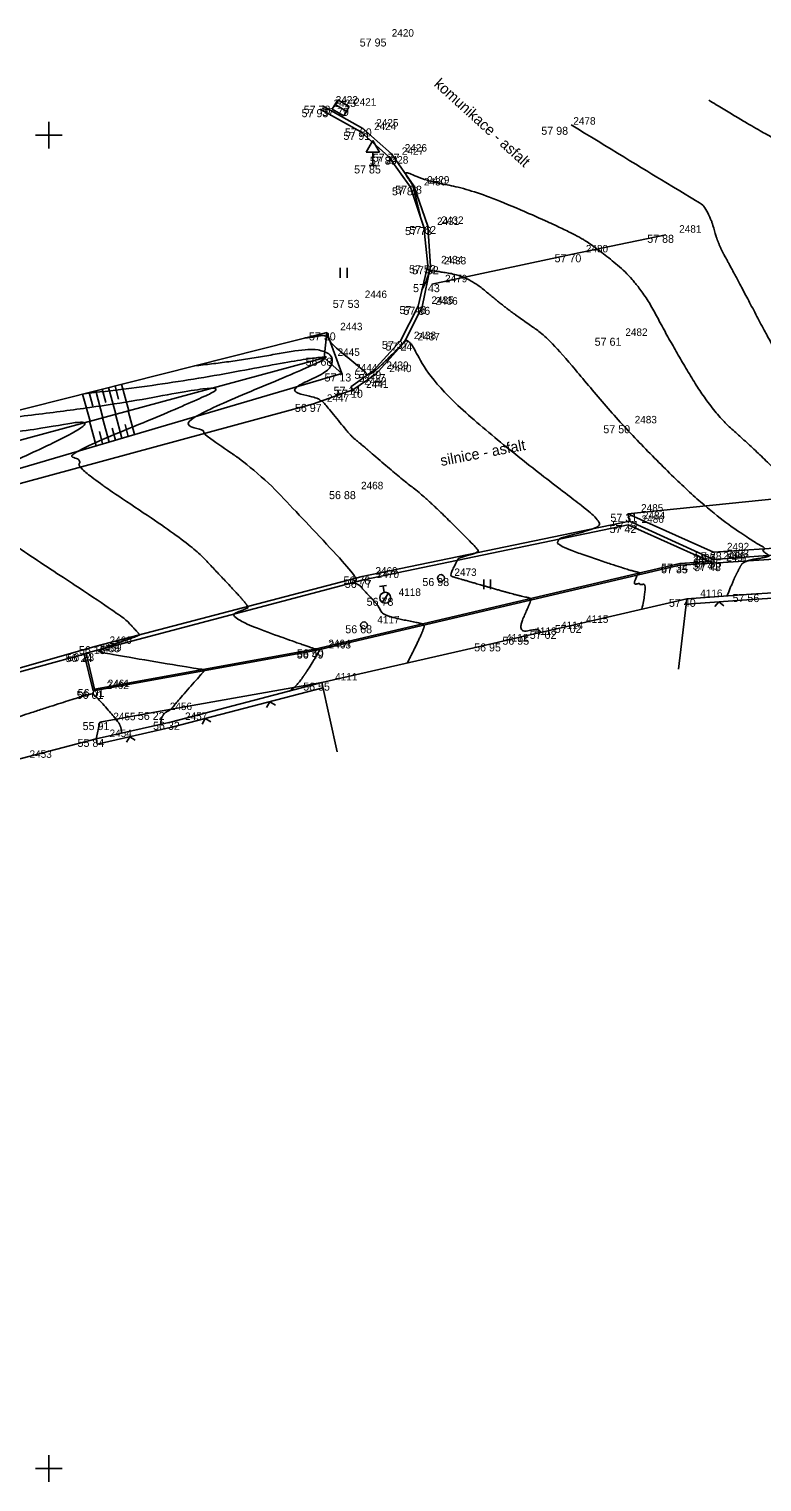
# Model space of a CAD drawing. Extents: x -704017 to -701500, y -1008977 to -1008450.
# Drawn here: x -702650.7 to -702623.3, y -1008800.5 to -1008746 of the extents above; entities that cross this region are included whole.
import ezdxf

# ---------------------------------------------------------------- set-up
doc = ezdxf.new("R2010")
doc.units = 0
for name, color, linetype in [('Z_ACO', 7, 'Continuous'), ('Z_body', 7, 'Continuous'), ('Z_body_cisla', 7, 'Continuous'), ('Z_body_vysky', 7, 'Continuous'), ('Z_budovy', 7, 'Continuous'), ('Z_chodnik', 7, 'Continuous'), ('Z_dopravni_znaceni', 7, 'Continuous'), ('Z_hekt_sit', 7, 'Continuous'), ('Z_komunikace', 7, 'Continuous'), ('Z_obruby', 7, 'Continuous'), ('Z_oploceni', 7, 'Continuous'), ('Z_popis', 7, 'Continuous'), ('Z_rozhrani_ploch', 7, 'Continuous'), ('Z_site_znaky_kanalizace', 7, 'Continuous'), ('Z_site_znaky_vodovod', 7, 'Continuous'), ('Z_teren_hrany_paty', 7, 'Continuous'), ('Z_vrstevnice_hlavni', 7, 'Continuous'), ('Z_vrstevnice_vedlejsi', 7, 'Continuous'), ('Z_vstupy', 7, 'Continuous')]:
    doc.layers.add(name, color=color, linetype=linetype)

# ---------------------------------------------------------------- blocks, each defined once
blk = doc.blocks.new('POINT_DISPLAY')
blk.add_line((0, 0), (0, 0))
blk = doc.blocks.new('Z212')
for p, q in [((-0.17, 0.17), (0, 0)), ((0, 0), (0.17, 0.17))]:
    blk.add_line(p, q)
blk = doc.blocks.new('Z306')
for p, q in [((-0.13, 0.17), (-0.13, -0.2)), ((0.13, 0.17), (0.13, -0.2))]:
    blk.add_line(p, q)
blk = doc.blocks.new('Z527')
for p, q in [((0, 0.93), (-0.25, 0.5)), ((0.25, 0.5), (0, 0.93)), ((-0.25, 0.5), (0.25, 0.5)), ((-0.13, 0), (0.13, 0)), ((0, 0), (0, 0.5))]:
    blk.add_line(p, q)
blk = doc.blocks.new('Z38')
for p, q in [((0.25, 0.2), (-0.25, 0.2)), ((-0.25, 0.2), (-0.25, -0.2)), ((-0.25, 0), (0.25, 0)), ((0.25, -0.2), (0.25, 0.2)), ((-0.25, -0.2), (0.25, -0.2))]:
    blk.add_line(p, q)
blk = doc.blocks.new('Z614')
for p, q in [((-0.13, 0.03), (-0.1, 0.08)), ((-0.13, -0.03), (-0.13, 0.03)), ((-0.1, 0.08), (-0.08, 0.1)), ((-0.08, 0.1), (-0.03, 0.13)), ((-0.03, 0.13), (0.03, 0.13)), ((0.03, 0.13), (0.08, 0.1)), ((0.08, 0.1), (0.1, 0.08)), ((0.1, 0.08), (0.13, 0.03)), ((0.13, 0.03), (0.13, -0.03)), ((-0.1, -0.08), (-0.13, -0.03)), ((-0.08, -0.1), (-0.1, -0.08)), ((-0.03, -0.13), (-0.08, -0.1)), ((0.03, -0.13), (-0.03, -0.13)), ((0.08, -0.1), (0.03, -0.13)), ((0.1, -0.08), (0.08, -0.1)), ((0.13, -0.03), (0.1, -0.08))]:
    blk.add_line(p, q)
blk = doc.blocks.new('Z18')
for p, q in [((-0.2, 0.05), (-0.15, 0.15)), ((-0.2, -0.05), (-0.2, 0.05)), ((-0.15, 0.15), (-0.05, 0.2)), ((0.15, 0.15), (-0.15, -0.15)), ((-0.13, 0.45), (0.13, 0.45)), ((-0.05, 0.2), (0.05, 0.2)), ((0, 0.2), (0, 0.45)), ((0.05, 0.2), (0.15, 0.15)), ((0.15, 0.15), (0.2, 0.05)), ((0.2, 0.05), (0.2, -0.05)), ((-0.15, -0.15), (-0.2, -0.05)), ((-0.05, -0.2), (-0.15, -0.15)), ((0.05, -0.2), (-0.05, -0.2)), ((0.15, -0.15), (0.05, -0.2)), ((0.2, -0.05), (0.15, -0.15))]:
    blk.add_line(p, q)

msp = doc.modelspace()

# ---------------------------------------------------------------- linework, layer by layer
at = {"layer": 'Z_ACO'}
for p, q in [((-702630.36, -1008754.47), (-702626.86, -1008753.74)), ((-702635.64, -1008755.59), (-702630.36, -1008754.47))]:
    msp.add_line(p, q, dxfattribs=at)
at = {"layer": 'Z_budovy'}
for p, q in [((-702630.35, -1008768.37), (-702626.07, -1008767.39)), ((-702626.39, -1008770.03), (-702626.07, -1008767.39)), ((-702639.76, -1008770.53), (-702633.35, -1008769.06)), ((-702632.29, -1008768.81), (-702631.29, -1008768.59)), ((-702639.76, -1008770.53), (-702639.18, -1008773.12))]:
    msp.add_line(p, q, dxfattribs=at)
at = {"layer": 'Z_chodnik'}
for p, q in [((-702640, -1008769.33), (-702626.34, -1008766.13)), ((-702626.34, -1008766.13), (-702625.1, -1008766.05)), ((-702648.67, -1008769.46), (-702648.33, -1008770.84)), ((-702648.33, -1008770.84), (-702640, -1008769.33)), ((-702645.96, -1008771.63), (-702639.76, -1008770.53)), ((-702648.08, -1008772.01), (-702645.96, -1008771.63)), ((-702648.08, -1008772.01), (-702648.22, -1008772.64))]:
    msp.add_line(p, q, dxfattribs=at)
at = {"layer": 'Z_hekt_sit'}
for p, q in [((-702650.5, -1008750), (-702649.5, -1008750)), ((-702650, -1008749.5), (-702650, -1008750.5)), ((-702650, -1008799.5), (-702650, -1008800.5)), ((-702650.5, -1008800), (-702649.5, -1008800))]:
    msp.add_line(p, q, dxfattribs=at)
at = {"layer": 'Z_komunikace'}
for p, q in [((-702639.74, -1008748.9), (-702638.22, -1008749.75)), ((-702638.22, -1008749.75), (-702637.15, -1008750.7)), ((-702637.15, -1008750.7), (-702636.31, -1008751.9)), ((-702636.31, -1008751.9), (-702635.78, -1008753.41)), ((-702635.78, -1008753.41), (-702635.68, -1008754.92)), ((-702635.68, -1008754.92), (-702636, -1008756.44)), ((-702636, -1008756.44), (-702636.67, -1008757.78)), ((-702636.67, -1008757.78), (-702637.73, -1008758.96)), ((-702637.73, -1008758.96), (-702638.6, -1008759.55)), ((-702638.6, -1008759.55), (-702640.07, -1008760.08)), ((-702655.23, -1008764.19), (-702640.07, -1008760.08)), ((-702628.29, -1008764.2), (-702616.13, -1008762.97)), ((-702638.25, -1008766.55), (-702628.22, -1008764.48)), ((-702628.22, -1008764.48), (-702628.29, -1008764.2)), ((-702648.22, -1008769.16), (-702638.25, -1008766.55)), ((-702652.66, -1008770.43), (-702648.22, -1008769.16))]:
    msp.add_line(p, q, dxfattribs=at)
at = {"layer": 'Z_obruby'}
for p, q in [((-702639.82, -1008749.03), (-702638.3, -1008749.88)), ((-702638.3, -1008749.88), (-702637.26, -1008750.81)), ((-702637.26, -1008750.81), (-702636.43, -1008751.96)), ((-702636.43, -1008751.96), (-702635.94, -1008753.45)), ((-702635.94, -1008753.45), (-702635.79, -1008754.88)), ((-702635.79, -1008754.88), (-702636.15, -1008756.41)), ((-702636.15, -1008756.41), (-702636.81, -1008757.72)), ((-702636.81, -1008757.72), (-702637.84, -1008758.84)), ((-702637.84, -1008758.84), (-702638.67, -1008759.44)), ((-702638.67, -1008759.44), (-702638.6, -1008759.55)), ((-702638.2, -1008766.68), (-702628.27, -1008764.62)), ((-702628.27, -1008764.62), (-702625.21, -1008765.99)), ((-702625.1, -1008766.05), (-702618.04, -1008765.58)), ((-702640.02, -1008769.28), (-702626.34, -1008766.07)), ((-702626.34, -1008766.07), (-702625.21, -1008765.99)), ((-702625.21, -1008765.99), (-702625.1, -1008766.05)), ((-702648.6, -1008769.43), (-702638.2, -1008766.68)), ((-702652.56, -1008770.53), (-702648.67, -1008769.46)), ((-702648.67, -1008769.46), (-702648.6, -1008769.43)), ((-702648.6, -1008769.43), (-702648.29, -1008770.77)), ((-702648.29, -1008770.77), (-702640.02, -1008769.28))]:
    msp.add_line(p, q, dxfattribs=at)
at = {"layer": 'Z_oploceni'}
for p, q in [((-702623.65, -1008767.41), (-702626.09, -1008767.59)), ((-702623.66, -1008767.21), (-702626.07, -1008767.39)), ((-702623.66, -1008767.21), (-702620.11, -1008767.01)), ((-702623.65, -1008767.41), (-702620.1, -1008767.21)), ((-702645.39, -1008772), (-702639.76, -1008770.53)), ((-702645.34, -1008772.19), (-702639.72, -1008770.73)), ((-702648.22, -1008772.64), (-702645.39, -1008772)), ((-702648.18, -1008772.84), (-702645.34, -1008772.19)), ((-702648.22, -1008772.64), (-702648.18, -1008772.84))]:
    msp.add_line(p, q, dxfattribs=at)
at = {"layer": 'Z_rozhrani_ploch'}
for p, q in [((-702628.29, -1008764.2), (-702625.07, -1008765.64)), ((-702628.22, -1008764.48), (-702625.08, -1008765.91)), ((-702625.07, -1008765.64), (-702618.08, -1008765.17)), ((-702625.08, -1008765.91), (-702618.06, -1008765.41))]:
    msp.add_line(p, q, dxfattribs=at)
at = {"layer": 'Z_teren_hrany_paty'}
for p, q in [((-702657.12, -1008761.83), (-702639.57, -1008757.4)), ((-702639.67, -1008758.35), (-702639.57, -1008757.4)), ((-702639.57, -1008757.4), (-702639.01, -1008758.94)), ((-702655.88, -1008762.74), (-702639.67, -1008758.35)), ((-702639.67, -1008758.35), (-702639.01, -1008758.94)), ((-702639.01, -1008758.94), (-702655.4, -1008763.76)), ((-702648.73, -1008759.71), (-702648.45, -1008760.73)), ((-702648.48, -1008759.65), (-702648.35, -1008760.16)), ((-702648.24, -1008759.59), (-702647.97, -1008760.6)), ((-702648, -1008759.53), (-702647.86, -1008760.03)), ((-702647.76, -1008759.47), (-702647.49, -1008760.47)), ((-702647.51, -1008759.41), (-702647.38, -1008759.9)), ((-702647.27, -1008759.34), (-702647, -1008760.34)), ((-702646.78, -1008761.23), (-702647.02, -1008760.34)), ((-702648.22, -1008761.65), (-702648.47, -1008760.73)), ((-702647.74, -1008761.51), (-702647.99, -1008760.6)), ((-702647.26, -1008761.37), (-702647.5, -1008760.47)), ((-702647.02, -1008761.3), (-702647.14, -1008760.85)), ((-702647.98, -1008761.58), (-702648.1, -1008761.12)), ((-702647.5, -1008761.44), (-702647.62, -1008760.99))]:
    msp.add_line(p, q, dxfattribs=at)
at = {"layer": 'Z_vrstevnice_hlavni'}
for points in [[(-702630.416, -1008749.616), (-702625.799, -1008752.432), (-702625.423, -1008752.633), (-702625.175, -1008753.161), (-702625.132, -1008753.263), (-702624.874, -1008754.143), (-702624.402, -1008754.984), (-702622.625, -1008758.355), (-702621.686, -1008759.908), (-702618.689, -1008762.539), (-702618.058, -1008763.165), (-702617.68, -1008763.433), (-702616.898, -1008763.837), (-702615.597, -1008764.737), (-702614.913, -1008765.015), (-702615.538, -1008765.241), (-702615.398, -1008765.284), (-702615.656, -1008765.318), (-702615.773, -1008765.464), (-702616.146, -1008766.635), (-702616.155, -1008766.801)], [(-702644.537, -1008758.654), (-702642.854, -1008758.475), (-702639.618, -1008757.86), (-702639.201, -1008758.77), (-702641.162, -1008759.573), (-702639.871, -1008759.866), (-702639.823, -1008759.967), (-702639.731, -1008759.958), (-702638.686, -1008761.277), (-702638.351, -1008761.533), (-702636.804, -1008762.872), (-702635.86, -1008763.587), (-702633.904, -1008765.525), (-702633.873, -1008765.647), (-702634.621, -1008765.848), (-702634.686, -1008765.951), (-702634.971, -1008766.52), (-702634.793, -1008766.58), (-702632.439, -1008767.26), (-702631.877, -1008767.369), (-702631.973, -1008767.427), (-702631.899, -1008767.432), (-702632.474, -1008768.694), (-702631.546, -1008768.475), (-702631.576, -1008768.653)], [(-702666.86, -1008764.305), (-702666.101, -1008764.107), (-702660.186, -1008763.092), (-702656.884, -1008762.487), (-702656.428, -1008762.338), (-702653.8, -1008762.059), (-702652.34, -1008761.781), (-702655.604, -1008763.327), (-702657.495, -1008764.162), (-702661.19, -1008765.431), (-702663.088, -1008766.219), (-702663.599, -1008766.55), (-702661.588, -1008767.639), (-702659.693, -1008768.918), (-702653.899, -1008769.76), (-702653.524, -1008770.446), (-702652.25, -1008771.87), (-702654.07, -1008772.42), (-702654.272, -1008773.671), (-702654.329, -1008773.727), (-702654.053, -1008773.693), (-702653.751, -1008773.641), (-702653.563, -1008773.532), (-702654.07, -1008772.42), (-702652.136, -1008772.219), (-702652.047, -1008772.104), (-702648.446, -1008770.943), (-702648.305, -1008770.957), (-702647.465, -1008771.9), (-702647.268, -1008772.215), (-702647.277, -1008772.427)]]:
    msp.add_open_spline(points, degree=2, dxfattribs=at)
at = {"layer": 'Z_vrstevnice_vedlejsi'}
for points in [[(-702625.246, -1008748.696), (-702623.588, -1008749.706), (-702622.428, -1008750.326), (-702621.664, -1008751.956), (-702621.534, -1008752.268), (-702620.738, -1008754.983), (-702619.282, -1008757.575), (-702618.616, -1008758.839), (-702618.263, -1008759.422), (-702616.166, -1008761.263), (-702614.267, -1008762.903), (-702613.979, -1008763.167), (-702612.493, -1008764.195), (-702610.955, -1008764.822), (-702611.336, -1008764.959), (-702610.961, -1008765.074), (-702611.65, -1008765.164), (-702611.724, -1008765.257), (-702611.96, -1008765.997), (-702611.994, -1008766.58)], [(-702636.049, -1008753.119), (-702636.203, -1008752.468), (-702636.337, -1008751.913), (-702636.429, -1008751.764), (-702636.73, -1008751.3), (-702635.872, -1008751.723), (-702633.993, -1008752.067), (-702630.444, -1008753.616), (-702629.388, -1008754.267), (-702627.833, -1008755.599), (-702626.635, -1008757.871), (-702625.108, -1008760.394), (-702623.609, -1008761.709), (-702621.765, -1008763.54), (-702620.66, -1008764.323), (-702618.912, -1008765.226), (-702619.551, -1008765.459), (-702619.464, -1008765.51), (-702619.558, -1008765.651), (-702619.846, -1008765.7), (-702620.538, -1008766.928), (-702620.594, -1008767.037)], [(-702636.006, -1008755.798), (-702635.915, -1008755.665), (-702635.72, -1008755.11), (-702635.671, -1008755.069), (-702634.271, -1008755.3), (-702633.011, -1008756.372), (-702632.013, -1008757.09), (-702631.196, -1008757.654), (-702628.53, -1008760.88), (-702625.472, -1008763.915), (-702623.64, -1008765.213), (-702623.073, -1008765.506), (-702623.28, -1008765.581), (-702622.974, -1008765.76), (-702623.009, -1008765.813), (-702623.951, -1008765.973), (-702624.102, -1008766.242), (-702624.325, -1008766.675), (-702624.564, -1008767.278)], [(-702640.398, -1008757.609), (-702640.117, -1008757.579), (-702639.578, -1008757.477), (-702639.405, -1008757.853), (-702638.133, -1008758.865), (-702638.061, -1008759), (-702638, -1008758.989), (-702637.803, -1008758.88), (-702637.362, -1008758.464), (-702636.681, -1008757.775), (-702636.648, -1008757.723), (-702636.614, -1008757.668), (-702636.459, -1008757.775), (-702636.357, -1008757.899), (-702635.5, -1008759.425), (-702632.667, -1008761.876), (-702629.755, -1008764.081), (-702629.377, -1008764.456), (-702629.314, -1008764.706), (-702630.841, -1008765.117), (-702630.867, -1008765.159), (-702630.982, -1008765.389), (-702628.578, -1008766.205), (-702627.955, -1008766.385), (-702627.806, -1008766.414), (-702627.949, -1008766.501), (-702627.928, -1008766.502), (-702628.093, -1008766.863), (-702627.828, -1008766.8), (-702627.84, -1008766.875), (-702627.555, -1008766.809), (-702627.759, -1008767.777)], [(-702648.676, -1008759.699), (-702645.59, -1008759.371), (-702639.659, -1008758.243), (-702639.567, -1008758.442), (-702645.301, -1008760.79), (-702644.133, -1008761.055), (-702644.239, -1008761.21), (-702642.257, -1008762.516), (-702640.469, -1008764.385), (-702638.413, -1008766.593), (-702638.523, -1008766.76), (-702638.585, -1008766.782), (-702638.335, -1008766.873), (-702638.196, -1008767.058), (-702637.62, -1008767.659), (-702637.506, -1008767.967), (-702636.924, -1008768.135), (-702635.949, -1008768.325), (-702635.996, -1008768.354), (-702635.87, -1008768.363), (-702636.241, -1008769.177), (-702636.555, -1008769.795)], [(-702652.815, -1008760.743), (-702648.327, -1008760.267), (-702643.024, -1008759.258), (-702644.913, -1008760.153), (-702649.44, -1008762.007), (-702648.751, -1008762.164), (-702648.976, -1008762.495), (-702644.741, -1008765.284), (-702643.699, -1008766.374), (-702642.5, -1008767.662), (-702642.564, -1008767.76), (-702643.4, -1008768.055), (-702640.02, -1008769.28), (-702639.841, -1008769.293), (-702639.855, -1008769.324), (-702639.96, -1008769.53), (-702640.699, -1008770.697), (-702640.984, -1008770.85)], [(-702656.954, -1008761.788), (-702651.064, -1008761.163), (-702647.682, -1008760.52), (-702652.196, -1008762.658), (-702653.579, -1008763.224), (-702653.368, -1008763.272), (-702653.714, -1008763.779), (-702647.226, -1008768.053), (-702646.928, -1008768.364), (-702646.586, -1008768.732), (-702646.604, -1008768.76), (-702648.215, -1008769.328), (-702647.964, -1008769.419), (-702644.239, -1008770.04), (-702644.145, -1008770.05), (-702644.165, -1008770.085), (-702645.298, -1008771.374), (-702645.396, -1008771.53), (-702645.789, -1008771.741), (-702645.803, -1008772.093)]]:
    msp.add_open_spline(points, degree=2, dxfattribs=at)
at = {"layer": 'Z_vstupy'}
for p, q in [((-702631.29, -1008768.59), (-702630.35, -1008768.37)), ((-702633.35, -1008769.06), (-702632.29, -1008768.81)), ((-702651.22, -1008773.42), (-702648.22, -1008772.64))]:
    msp.add_line(p, q, dxfattribs=at)

# ---------------------------------------------------------------- block references
at = {"layer": 'Z_body'}
for p in [(-702637.64, -1008746.38), (-702639.74, -1008748.9), (-702639.82, -1008749.03), (-702639.05, -1008748.98), (-702638.3, -1008749.88), (-702638.22, -1008749.75), (-702630.83, -1008749.69), (-702637.26, -1008750.81), (-702637.15, -1008750.7), (-702637.85, -1008751.14), (-702636.43, -1008751.96), (-702636.31, -1008751.9), (-702635.94, -1008753.45), (-702635.78, -1008753.41), (-702626.86, -1008753.74), (-702635.79, -1008754.88), (-702630.36, -1008754.47), (-702635.68, -1008754.92), (-702635.64, -1008755.59), (-702638.65, -1008756.18), (-702636.15, -1008756.41), (-702636, -1008756.44), (-702639.57, -1008757.4), (-702628.88, -1008757.6), (-702636.81, -1008757.72), (-702636.67, -1008757.78), (-702639.67, -1008758.35), (-702639.01, -1008758.94), (-702637.84, -1008758.84), (-702637.73, -1008758.96), (-702638.67, -1008759.44), (-702638.6, -1008759.55), (-702640.07, -1008760.08), (-702628.53, -1008760.88), (-702638.79, -1008763.35), (-702628.29, -1008764.2), (-702628.27, -1008764.62), (-702628.22, -1008764.48), (-702625.07, -1008765.64), (-702626.34, -1008766.07), (-702626.34, -1008766.13), (-702625.21, -1008765.99), (-702625.1, -1008766.05), (-702625.08, -1008765.91), (-702638.25, -1008766.55), (-702638.2, -1008766.68), (-702635.29, -1008766.61), (-702637.38, -1008767.35), (-702626.07, -1008767.39), (-702623.66, -1008767.21), (-702638.18, -1008768.38), (-702630.35, -1008768.37), (-702633.35, -1008769.06), (-702632.29, -1008768.81), (-702631.29, -1008768.59), (-702648.67, -1008769.46), (-702648.6, -1008769.43), (-702648.22, -1008769.16), (-702640.02, -1008769.28), (-702640, -1008769.33), (-702639.76, -1008770.53), (-702648.33, -1008770.84), (-702648.29, -1008770.77), (-702645.96, -1008771.63), (-702648.08, -1008772.01), (-702645.39, -1008772), (-702648.22, -1008772.64)]:
    msp.add_blockref('POINT_DISPLAY', p, dxfattribs=at)
at = {"layer": 'Z_dopravni_znaceni'}
msp.add_blockref('Z527', (-702637.85, -1008751.14), dxfattribs=at)
at = {"layer": 'Z_oploceni'}
for p, rotation in [((-702624.87, -1008767.5), -175.70000000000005), ((-702641.71, -1008771.25), -165.40000000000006), ((-702644.13, -1008771.88), -165.40000000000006), ((-702646.96, -1008772.56), -167.30000000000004)]:
    msp.add_blockref('Z212', p, dxfattribs=dict(at, rotation=rotation))
at = {"layer": 'Z_popis'}
for p in [(-702638.94, -1008755.15), (-702633.56, -1008766.83)]:
    msp.add_blockref('Z306', p, dxfattribs=at)
at = {"layer": 'Z_site_znaky_kanalizace', "rotation": -30.60000000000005}
msp.add_blockref('Z38', (-702639.05, -1008748.98), dxfattribs=at)
at = {"layer": 'Z_site_znaky_vodovod', "rotation": 10.799999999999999}
for name, p in [('Z18', (-702637.38, -1008767.35)), ('Z614', (-702635.29, -1008766.61)), ('Z614', (-702638.18, -1008768.38))]:
    msp.add_blockref(name, p, dxfattribs=at)

# ---------------------------------------------------------------- texts
at = {"layer": 'Z_body_cisla'}
for s, p in [('2420', (-702637.14, -1008746.31)), ('2423', (-702639.32, -1008748.95)), ('2422', (-702639.24, -1008748.82)), ('2421', (-702638.55, -1008748.9)), ('2425', (-702637.72, -1008749.68)), ('2478', (-702630.33, -1008749.61)), ('2424', (-702637.8, -1008749.81)), ('2427', (-702636.76, -1008750.74)), ('2426', (-702636.65, -1008750.62)), ('2428', (-702637.35, -1008751.07)), ('2430', (-702635.93, -1008751.89)), ('2429', (-702635.81, -1008751.82)), ('2431', (-702635.44, -1008753.37)), ('2432', (-702635.28, -1008753.33)), ('2481', (-702626.36, -1008753.66)), ('2480', (-702629.86, -1008754.4)), ('2434', (-702635.29, -1008754.81)), ('2433', (-702635.18, -1008754.85)), ('2479', (-702635.14, -1008755.52)), ('2446', (-702638.15, -1008756.11)), ('2435', (-702635.65, -1008756.33)), ('2436', (-702635.5, -1008756.36)), ('2443', (-702639.07, -1008757.32)), ('2438', (-702636.31, -1008757.65)), ('2437', (-702636.17, -1008757.7)), ('2482', (-702628.38, -1008757.53)), ('2445', (-702639.17, -1008758.28)), ('2444', (-702638.51, -1008758.86)), ('2439', (-702637.34, -1008758.77)), ('2440', (-702637.23, -1008758.89)), ('2442', (-702638.17, -1008759.36)), ('2441', (-702638.1, -1008759.48)), ('2447', (-702639.57, -1008760)), ('2483', (-702628.03, -1008760.81)), ('2468', (-702638.29, -1008763.28)), ('2485', (-702627.79, -1008764.12)), ('2484', (-702627.72, -1008764.4)), ('2486', (-702627.77, -1008764.54)), ('2495', (-702625.84, -1008765.99)), ('2494', (-702625.84, -1008766.06)), ('2496', (-702624.71, -1008765.91)), ('2497', (-702624.6, -1008765.98)), ('2493', (-702624.58, -1008765.83)), ('2492', (-702624.57, -1008765.57)), ('2469', (-702637.75, -1008766.48)), ('2470', (-702637.7, -1008766.61)), ('2473', (-702634.79, -1008766.53)), ('4118', (-702636.88, -1008767.28)), ('4116', (-702625.57, -1008767.32)), ('4117', (-702637.68, -1008768.31)), ('4113', (-702631.79, -1008768.74)), ('4114', (-702630.79, -1008768.52)), ('4115', (-702629.85, -1008768.29)), ('2459', (-702648.1, -1008769.36)), ('2460', (-702647.72, -1008769.08)), ('2464', (-702639.52, -1008769.2)), ('2463', (-702639.5, -1008769.25)), ('4112', (-702632.85, -1008768.99)), ('2458', (-702648.17, -1008769.39)), ('4111', (-702639.26, -1008770.45)), ('2462', (-702647.83, -1008770.77)), ('2461', (-702647.79, -1008770.7)), ('2455', (-702647.58, -1008771.94)), ('2456', (-702645.46, -1008771.56)), ('2457', (-702644.89, -1008771.93)), ('2454', (-702647.72, -1008772.57)), ('2453', (-702650.72, -1008773.35))]:
    msp.add_text(s, height=0.28, dxfattribs=at).set_placement(p)
at = {"layer": 'Z_body_vysky'}
for s, p in [('57 95', (-702638.34, -1008746.68)), ('57 78', (-702640.44, -1008749.2)), ('57 93', (-702640.52, -1008749.33)), ('57 79', (-702639.75, -1008749.28)), ('57 91', (-702638.95, -1008750.18)), ('57 80', (-702638.895, -1008750.05)), ('57 98', (-702631.53, -1008749.99)), ('57 89', (-702637.96, -1008751.11)), ('57 77', (-702637.85, -1008751)), ('57 85', (-702638.55, -1008751.44)), ('57 82', (-702637.13, -1008752.26)), ('57 73', (-702637.01, -1008752.2)), ('57 73', (-702636.64, -1008753.75)), ('57 62', (-702636.48, -1008753.71)), ('57 88', (-702627.56, -1008754.04)), ('57 53', (-702636.49, -1008755.18)), ('57 52', (-702636.38, -1008755.22)), ('57 70', (-702631.035, -1008754.77)), ('57 43', (-702636.34, -1008755.89)), ('57 53', (-702639.35, -1008756.48)), ('57 48', (-702636.85, -1008756.71)), ('57 36', (-702636.7, -1008756.74)), ('57 30', (-702640.245, -1008757.7)), ('57 61', (-702629.53, -1008757.9)), ('57 37', (-702637.51, -1008758.02)), ('57 24', (-702637.37, -1008758.08)), ('56 68', (-702640.37, -1008758.65)), ('57 13', (-702639.66, -1008759.24)), ('57 29', (-702638.54, -1008759.14)), ('57 17', (-702638.38, -1008759.26)), ('57 14', (-702639.32, -1008759.74)), ('57 10', (-702639.225, -1008759.85)), ('56 97', (-702640.77, -1008760.38)), ('57 50', (-702629.205, -1008761.18)), ('56 88', (-702639.49, -1008763.65)), ('57 42', (-702628.97, -1008764.92)), ('57 31', (-702628.94, -1008764.5)), ('57 31', (-702628.87, -1008764.78)), ('57 38', (-702625.77, -1008765.94)), ('57 34', (-702627.04, -1008766.37)), ('57 35', (-702627.04, -1008766.43)), ('57 41', (-702625.86, -1008766.29)), ('57 43', (-702625.8, -1008766.35)), ('57 35', (-702625.78, -1008766.21)), ('56 76', (-702638.95, -1008766.85)), ('56 77', (-702638.9, -1008766.98)), ('56 98', (-702635.99, -1008766.91)), ('56 78', (-702638.08, -1008767.65)), ('57 40', (-702626.745, -1008767.69)), ('57 56', (-702624.36, -1008767.51)), ('56 68', (-702638.88, -1008768.68)), ('57 02', (-702631.025, -1008768.67)), ('56 95', (-702634.05, -1008769.36)), ('56 95', (-702632.99, -1008769.11)), ('57 02', (-702631.965, -1008768.89)), ('56 24', (-702649.37, -1008769.76)), ('56 23', (-702649.3, -1008769.73)), ('56 15', (-702648.87, -1008769.46)), ('56 49', (-702640.7, -1008769.63)), ('56 50', (-702640.695, -1008769.58)), ('56 55', (-702640.46, -1008770.83)), ('56 01', (-702648.955, -1008771.14)), ('56 01', (-702648.915, -1008771.07)), ('56 22', (-702646.66, -1008771.93)), ('55 91', (-702648.73, -1008772.31)), ('56 32', (-702646.09, -1008772.3)), ('55 84', (-702648.92, -1008772.94))]:
    msp.add_text(s, height=0.3, dxfattribs=at).set_placement(p)
at = {"layer": 'Z_popis'}
for s, rotation, p in [('komunikace - asfalt', 317.7, (-702635.58, -1008748.13)), ('silnice - asfalt', 10.8, (-702635.28, -1008762.41))]:
    msp.add_text(s, height=0.4, rotation=rotation, dxfattribs=at).set_placement(p)

doc.saveas('drawing.dxf')
